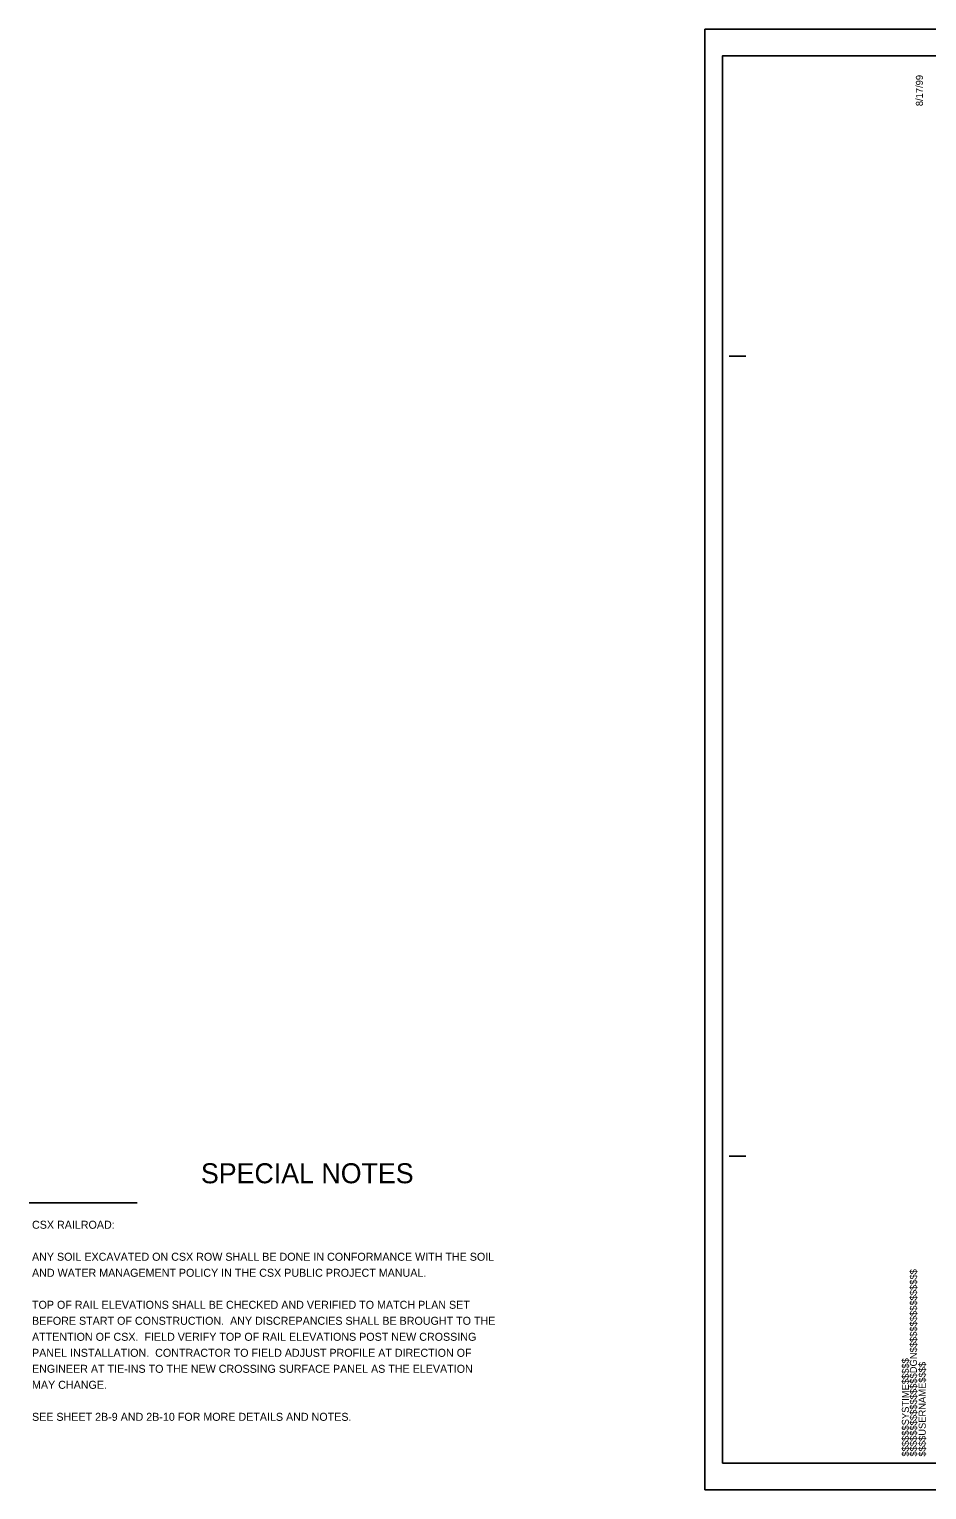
# Model space of a CAD drawing. Extents: x -1492 to 2447, y -56 to 1953.
# Drawn here: x -673 to 0, y -22 to 1072 of the extents above; entities that cross this region are included whole.
import ezdxf

# ---------------------------------------------------------------- set-up
doc = ezdxf.new("R2010")
doc.units = 0
for name, color, linetype in [('Sheet Cutting Line CELL', 7, 'Continuous'), ('Sheet Data Field CELL', 7, 'Continuous'), ('Sheet Data Text CELL', 7, 'Continuous'), ('Sheet Plan CELL', 7, 'Continuous'), ('Sheet Plot Border Inside CELL', 7, 'Continuous'), ('Sheet Plot Border Outside CELL', 7, 'Continuous')]:
    doc.layers.add(name, color=color, linetype=linetype)

msp = doc.modelspace()

# ---------------------------------------------------------------- linework, layer by layer
at = {"layer": 'Sheet Cutting Line CELL'}
for p, q in [((1517, 1072.5), (-166.5, 1072.5)), ((-166.5, 1072.5), (-166.5, -22.5)), ((-166.5, -22.5), (1517, -22.5))]:
    msp.add_line(p, q, dxfattribs=at)
at = {"layer": 'Sheet Data Text CELL'}
msp.add_line((-673, 192.7), (-592.1, 192.7), dxfattribs=at)
at = {"layer": 'Sheet Plan CELL'}
for p, q in [((-148.5, 827.5), (-136, 827.5)), ((-148.5, 227.5), (-136, 227.5))]:
    msp.add_line(p, q, dxfattribs=at)
at = {"layer": 'Sheet Plot Border Inside CELL'}
msp.add_lwpolyline([(-153.5, -2.5), (1512.5, -2.5), (1512.5, 1052.5), (-153.5, 1052.5)], close=True, dxfattribs=at)
at = {"layer": 'Sheet Plot Border Outside CELL'}
msp.add_lwpolyline([(-166.5, -22.5), (1517, -22.5), (1517, 1072.5), (-166.5, 1072.5)], close=True, dxfattribs=at)

# ---------------------------------------------------------------- texts
at = {"layer": 'Sheet Data Field CELL'}
msp.add_text('SPECIAL NOTES', height=15, dxfattribs=at).set_placement((-544.3, 207.3))
at = {"layer": 'Sheet Data Text CELL'}
for s, p in [('CSX RAILROAD:', (-670.9, 173.2)), ('ANY SOIL EXCAVATED ON CSX ROW SHALL BE DONE IN CONFORMANCE WITH THE SOIL ', (-670.9, 149.2)), ('AND WATER MANAGEMENT POLICY IN THE CSX PUBLIC PROJECT MANUAL.', (-670.9, 137.2)), ('TOP OF RAIL ELEVATIONS SHALL BE CHECKED AND VERIFIED TO MATCH PLAN SET ', (-670.9, 113.2)), ('BEFORE START OF CONSTRUCTION.  ANY DISCREPANCIES SHALL BE BROUGHT TO THE ', (-670.9, 101.2)), ('ATTENTION OF CSX.  FIELD VERIFY TOP OF RAIL ELEVATIONS POST NEW CROSSING ', (-670.9, 89.2)), ('PANEL INSTALLATION.  CONTRACTOR TO FIELD ADJUST PROFILE AT DIRECTION OF ', (-670.9, 77.2)), ('ENGINEER AT TIE-INS TO THE NEW CROSSING SURFACE PANEL AS THE ELEVATION ', (-670.9, 65.2)), ('MAY CHANGE.', (-670.9, 53.2)), ('SEE SHEET 2B-9 AND 2B-10 FOR MORE DETAILS AND NOTES.', (-670.9, 29.2))]:
    msp.add_text(s, height=6, dxfattribs=at).set_placement(p)
at = {"layer": 'Sheet Plan CELL'}
for s, p in [('8/17/99', (-3.2, 1014.8)), ('$$$$$$$$$$$$$$$$DGN$$$$$$$$$$$$$$$$', (-7.7, 2.4)), ('$$$$$$SYSTIME$$$$$', (-13.7, 2.4)), ('$$$$USERNAME$$$$', (-1.1, 2.4))]:
    msp.add_text(s, height=5.25, rotation=90, dxfattribs=at).set_placement(p)

doc.saveas('drawing.dxf')
